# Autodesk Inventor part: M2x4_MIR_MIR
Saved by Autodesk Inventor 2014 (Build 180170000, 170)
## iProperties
Created: 2015-05
Part Number: M2x4_MIR_MIR
Material: 일반
Vendor: CBT Solutions
Document SubType Name: 모델링
Designer: Administrator
Appearance: 기본값
Company: 한국ATC센터
Author: KYOUNG IL JANG
Comments: 파생
d0: 1.000 ul
d0_1: 1.000 ul
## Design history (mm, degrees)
derived "M2x4_MIR.ipt"
feature "솔리드1::M2x4_MIR.ipt"
tag "피쳐 태그1"
node "솔리드1"
other parameters: "d0" = 1, "d0_1" = 1
